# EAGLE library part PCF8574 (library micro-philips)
I2C-Bus Remote 8-bit I/O expander http://www.semiconductors.philips.com/acrobat_download/datasheets/PCF8574_4.pdf
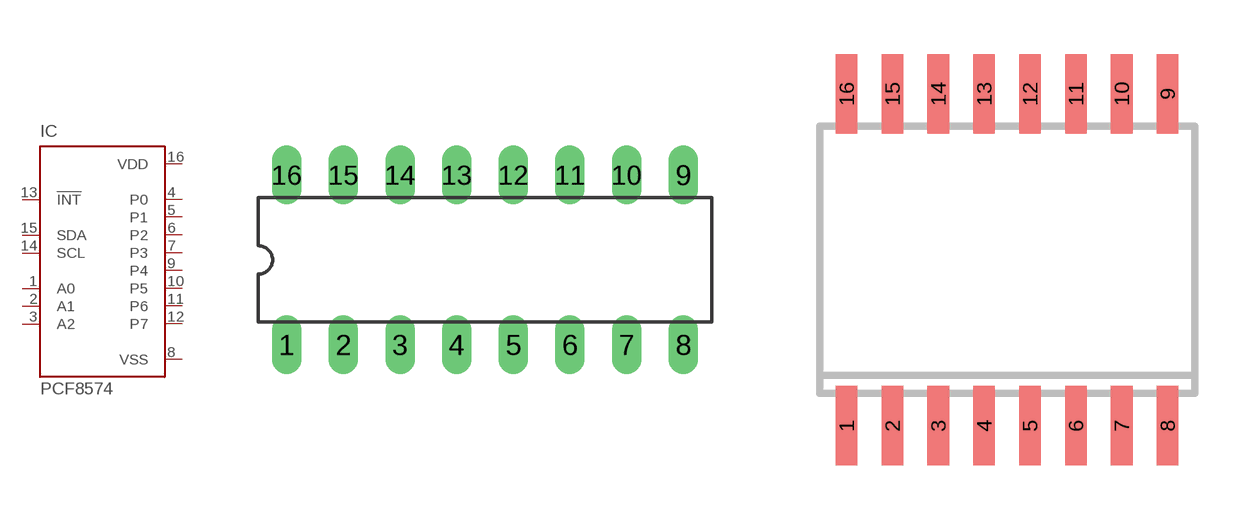
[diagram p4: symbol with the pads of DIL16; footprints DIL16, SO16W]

Designator prefix IC

## PCF8574P (MPN: PCF8574PN; OC_FARNELL: 204020; OC_NEWARK: 11N8515)  [DIL16]
1  A0  in
2  A1  in
3  A2  in
4  P0
5  P1
6  P2
7  P3
8  VSS  pwr
9  P4
10  P5
11  P6
12  P7
13  !INT  out
14  SCL  in
15  SDA
16  VDD  pwr

## PCF8574T (MPN: PCF8574T/3,512; OC_FARNELL: 1201255; OC_NEWARK: 70R6870)  [SO16W]
Pads as for DIL16

## PCF8574TS (MPN: PCF8574TS/3,118; OC_FARNELL: 1506644; OC_NEWARK: 70R6873)  [SSOP20]
1  !INT  out
2  SCL  in
4  SDA
5  VDD  pwr
6  A0  in
7  A1  in
9  A2  in
10  P0
11  P1
12  P2
14  P3
15  VSS  pwr
16  P4
17  P5
19  P6
20  P7

## Footprint DIL16 (pad centres in mm)
Dual In Line
drill 0.813 long: 1 -8.89,-3.81; 2 -6.35,-3.81; 3 -3.81,-3.81; 4 -1.27,-3.81; 5 1.27,-3.81; 6 3.81,-3.81; 7 6.35,-3.81; 8 8.89,-3.81; 9 8.89,3.81; 10 6.35,3.81; 11 3.81,3.81; 12 1.27,3.81; 13 -1.27,3.81; 14 -3.81,3.81; 15 -6.35,3.81; 16 -8.89,3.81

## Footprint SO16W (pad centres in mm)
Small Outline Package 7.6 x 10.6 mm
smd 0.6 x 2.2: 1 -4.445,-4.6; 2 -3.175,-4.6; 3 -1.905,-4.6; 4 -0.635,-4.6; 5 0.635,-4.6; 6 1.905,-4.6; 7 3.175,-4.6; 8 4.445,-4.6; 9 4.445,4.6; 10 3.175,4.6; 11 1.905,4.6; 12 0.635,4.6; 13 -0.635,4.6; 14 -1.905,4.6; 15 -3.175,4.6; 16 -4.445,4.6

## Footprint SSOP20 (pad centres in mm)
plastic shrink small outline package 20 leads; body width 4.4 mm SOT266-1 Source: http://www.semiconductors.philips.com/acrobat_download/datasheets/PCF8574_4.pdf
smd 0.35 x 1.2: 1 -2.925,-2.85; 2 -2.275,-2.85; 3 -1.625,-2.85; 4 -0.975,-2.85; 5 -0.325,-2.85; 6 0.325,-2.85; 7 0.975,-2.85; 8 1.625,-2.85; 9 2.275,-2.85; 10 2.925,-2.85; 11 2.925,2.85; 12 2.275,2.85; 13 1.625,2.85; 14 0.975,2.85; 15 0.325,2.85; 16 -0.325,2.85; 17 -0.975,2.85; 18 -1.625,2.85; 19 -2.275,2.85; 20 -2.925,2.85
